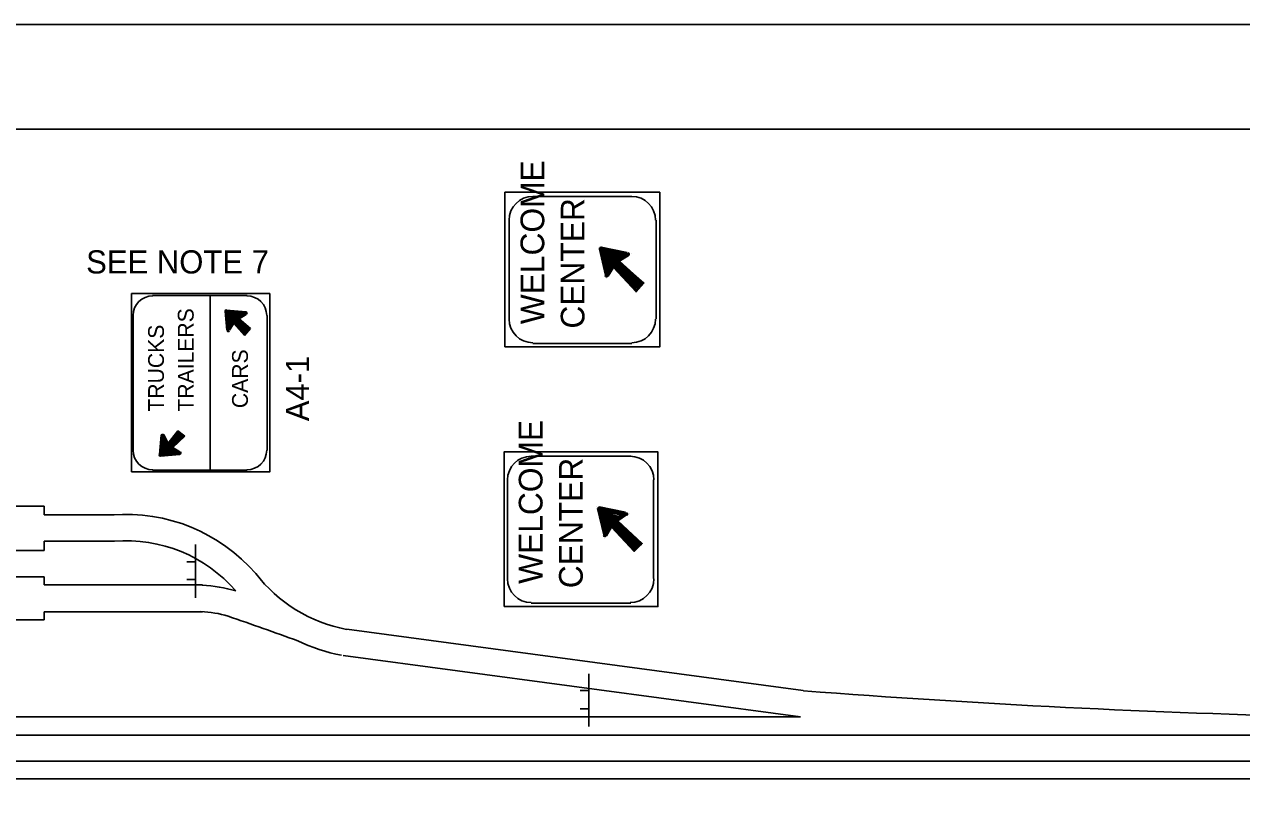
# Model space of a CAD drawing. Extents: x 2189973 to 2192941, y 2147557 to 2151454.
# Drawn here: x 2190575 to 2191146, y 2151094 to 2151454 of the extents above; entities that cross this region are included whole.
import ezdxf

# ---------------------------------------------------------------- set-up
doc = ezdxf.new("R2010")
doc.units = 0
doc.layers.add('Default', color=7, linetype='Continuous')
doc.layers.add('PLT-BNDY', color=7, linetype='Continuous')

msp = doc.modelspace()

# ---------------------------------------------------------------- linework, layer by layer
at = {"layer": 'Default'}
for p, q in [((2190104.48, 2151405.2), (2192683.21, 2151405.2)), ((2190813.55, 2151373.62), (2190859.89, 2151373.62)), ((2190844.31, 2151349.83), (2190844.31, 2151349.83)), ((2190844.72, 2151349.01), (2190847.59, 2151336.71)), ((2190857.84, 2151347.37), (2190845.54, 2151349.83)), ((2190854.15, 2151343.27), (2190858.66, 2151346.14)), ((2190859.89, 2151346.96), (2190859.89, 2151346.96)), ((2190848.82, 2151336.3), (2190851.28, 2151340.4)), ((2190851.28, 2151340.4), (2190851.28, 2151340.4)), ((2190851.28, 2151340.4), (2190861.94, 2151328.92)), ((2190854.15, 2151343.27), (2190854.15, 2151343.27)), ((2190865.63, 2151333.02), (2190854.15, 2151343.27)), ((2190848, 2151335.07), (2190848, 2151335.07)), ((2190861.94, 2151328.92), (2190865.63, 2151333.02)), ((2190635.15, 2151327.28), (2190679.45, 2151327.28)), ((2190662.22, 2151245.26), (2190662.22, 2151327.28)), ((2190669.19, 2151319.9), (2190670.01, 2151310.87)), ((2190679.04, 2151319.49), (2190669.6, 2151320.31)), ((2190669.6, 2151319.9), (2190669.6, 2151319.9)), ((2190675.76, 2151316.2), (2190679.04, 2151318.26)), ((2190675.76, 2151316.2), (2190675.76, 2151316.2)), ((2190681.09, 2151311.69), (2190675.76, 2151316.2)), ((2190679.04, 2151318.67), (2190679.04, 2151318.67)), ((2190679.86, 2151318.67), (2190679.86, 2151318.67)), ((2190679.86, 2151318.67), (2190679.86, 2151318.67)), ((2190670.42, 2151310.87), (2190670.42, 2151310.87)), ((2190673.29, 2151314.15), (2190671.24, 2151310.87)), ((2190673.29, 2151314.15), (2190673.29, 2151314.15)), ((2190673.29, 2151314.15), (2190678.22, 2151308.41)), ((2190674.52, 2151315.38), (2190674.52, 2151315.38)), ((2190678.22, 2151308.41), (2190681.09, 2151311.69)), ((2190681.09, 2151311.69), (2190681.09, 2151311.69)), ((2190670.42, 2151309.64), (2190670.42, 2151309.64)), ((2190670.42, 2151309.64), (2190670.42, 2151309.64)), ((2190678.22, 2151308.41), (2190678.22, 2151308.41)), ((2190859.89, 2151304.72), (2190813.55, 2151304.72)), ((2190873.02, 2151303.08), (2190800.43, 2151303.08)), ((2190639.26, 2151261.66), (2190638.44, 2151252.64)), ((2190640.08, 2151262.48), (2190640.08, 2151262.48)), ((2190640.08, 2151262.48), (2190640.08, 2151262.48)), ((2190640.08, 2151261.66), (2190640.08, 2151261.66)), ((2190642.54, 2151257.97), (2190640.49, 2151262.07)), ((2190647.05, 2151263.71), (2190642.54, 2151257.97)), ((2190644.59, 2151255.92), (2190650.33, 2151261.25)), ((2190647.05, 2151263.71), (2190647.05, 2151263.71)), ((2190650.33, 2151261.25), (2190647.05, 2151263.71)), ((2190650.33, 2151261.25), (2190650.33, 2151261.25)), ((2190642.54, 2151257.97), (2190642.54, 2151257.97)), ((2190643.36, 2151257.15), (2190643.36, 2151257.15)), ((2190644.59, 2151255.92), (2190644.59, 2151255.92)), ((2190644.59, 2151255.92), (2190647.87, 2151253.87)), ((2190647.87, 2151253.46), (2190647.87, 2151253.46)), ((2190648.69, 2151253.46), (2190648.69, 2151253.46)), ((2190648.69, 2151253.46), (2190648.69, 2151253.46)), ((2190638.44, 2151252.23), (2190638.44, 2151252.23)), ((2190638.44, 2151252.23), (2190638.44, 2151252.23)), ((2190638.85, 2151252.64), (2190638.85, 2151252.64)), ((2190638.85, 2151251.82), (2190647.87, 2151252.64)), ((2190812.73, 2151251.82), (2190859.48, 2151251.82)), ((2190633.92, 2151244.44), (2190627.77, 2151244.44)), ((2190635.15, 2151245.26), (2190679.45, 2151245.26)), ((2190663.86, 2151244.44), (2190659.35, 2151244.44)), ((2190510.07, 2151228.44), (2190584.3, 2151228.44)), ((2190584.3, 2151224.34), (2190584.3, 2151228.44)), ((2190843.49, 2151228.03), (2190843.49, 2151228.03)), ((2190843.9, 2151227.21), (2190846.77, 2151214.91)), ((2190857.02, 2151225.57), (2190844.72, 2151228.03)), ((2190859.07, 2151225.16), (2190859.07, 2151225.16)), ((2190584.3, 2151224.34), (2190617.11, 2151224.34)), ((2190853.33, 2151221.47), (2190857.43, 2151224.34)), ((2190853.33, 2151221.47), (2190853.33, 2151221.47)), ((2190864.81, 2151210.81), (2190853.33, 2151221.47)), ((2190847.18, 2151213.27), (2190847.18, 2151213.27)), ((2190848, 2151214.5), (2190850.46, 2151218.6)), ((2190850.46, 2151218.6), (2190850.46, 2151218.6)), ((2190850.46, 2151218.6), (2190861.12, 2151207.12)), ((2190510.07, 2151207.53), (2190584.3, 2151207.53)), ((2190584.3, 2151207.53), (2190584.3, 2151212.04)), ((2190584.3, 2151212.04), (2190617.11, 2151212.04)), ((2190655.25, 2151185.38), (2190655.25, 2151210.4)), ((2190861.12, 2151207.12), (2190864.81, 2151210.81)), ((2190655.25, 2151202.2), (2190651.15, 2151202.2)), ((2190510.07, 2151195.22), (2190584.3, 2151195.22)), ((2190584.3, 2151195.22), (2190584.3, 2151191.53)), ((2190584.3, 2151191.53), (2190658.53, 2151191.53)), ((2190655.25, 2151193.99), (2190651.15, 2151193.99)), ((2190872.19, 2151181.28), (2190800.02, 2151181.28)), ((2190859.48, 2151182.92), (2190812.73, 2151182.92)), ((2190510.07, 2151175.13), (2190584.3, 2151175.13)), ((2190584.3, 2151178.82), (2190584.3, 2151175.13)), ((2190584.3, 2151178.82), (2190658.53, 2151178.82)), ((2190726.2, 2151170.62), (2190940.27, 2151141.91)), ((2190724.56, 2151158.31), (2190724.56, 2151158.31)), ((2190724.56, 2151158.31), (2190939.04, 2151129.61)), ((2190839.8, 2151125.1), (2190839.8, 2151149.7)), ((2190839.8, 2151141.91), (2190835.7, 2151141.91)), ((2190839.8, 2151133.3), (2190835.7, 2151133.3)), ((2190155.33, 2151129.61), (2190939.04, 2151129.61)), ((2190939.04, 2151129.61), (2190939.04, 2151129.61)), ((2190939.04, 2151129.61), (2190939.04, 2151129.61)), ((2190114.32, 2151121), (2192679.93, 2151121)), ((2190114.32, 2151108.69), (2192679.93, 2151108.69)), ((2190114.32, 2151100.49), (2192679.93, 2151100.49))]:
    msp.add_line(p, q, dxfattribs=at)
for points in [[(2190800.43, 2151303.08), (2190800.43, 2151375.67), (2190807.81, 2151375.67), (2190818.88, 2151375.67), (2190826.67, 2151375.67), (2190837.75, 2151375.67), (2190844.31, 2151375.67), (2190866.04, 2151375.67), (2190873.02, 2151375.67), (2190873.02, 2151375.67), (2190873.02, 2151303.08), (2190873.02, 2151303.08)], [(2190802.48, 2151316.2), (2190802.48, 2151362.55)], [(2190871.37, 2151362.55), (2190871.37, 2151316.2)], [(2190861.94, 2151328.92), (2190851.28, 2151340.4), (2190848.82, 2151336.3), (2190848, 2151336.3), (2190847.59, 2151336.71), (2190844.72, 2151349.01), (2190845.13, 2151349.42), (2190845.54, 2151349.83), (2190857.84, 2151346.96), (2190858.66, 2151346.55), (2190857.84, 2151346.14), (2190853.74, 2151343.27), (2190865.63, 2151333.02), (2190861.94, 2151328.92), (2190851.28, 2151340.81), (2190848.41, 2151336.3), (2190848, 2151336.3), (2190848, 2151336.71), (2190845.13, 2151349.01), (2190845.13, 2151349.42), (2190845.54, 2151349.42), (2190857.84, 2151346.96), (2190857.84, 2151346.55), (2190857.84, 2151346.14), (2190853.74, 2151343.27), (2190865.22, 2151333.02), (2190861.94, 2151329.33), (2190851.28, 2151340.81), (2190848.41, 2151336.71), (2190848, 2151336.71), (2190848, 2151336.71), (2190845.13, 2151349.42), (2190857.84, 2151346.55), (2190853.33, 2151343.27), (2190864.81, 2151332.61), (2190861.94, 2151329.74), (2190851.28, 2151341.22), (2190848, 2151336.71), (2190845.54, 2151349.01)], [(2190848.41, 2151337.12), (2190845.54, 2151349.42), (2190857.84, 2151346.55), (2190852.92, 2151343.27), (2190864.81, 2151332.61), (2190861.94, 2151329.74), (2190851.28, 2151341.22), (2190848.41, 2151337.53), (2190846.36, 2151349.01), (2190857.43, 2151346.55), (2190852.92, 2151343.27), (2190864.4, 2151332.61), (2190861.94, 2151330.15), (2190851.28, 2151341.63), (2190848.41, 2151337.94), (2190846.36, 2151348.6), (2190856.61, 2151346.14), (2190852.51, 2151343.27), (2190863.99, 2151332.61), (2190861.94, 2151330.97), (2190851.28, 2151341.63), (2190848.82, 2151338.76), (2190846.77, 2151348.19), (2190855.79, 2151346.14), (2190852.1, 2151343.27), (2190863.58, 2151333.02), (2190861.94, 2151330.97), (2190851.28, 2151342.04), (2190848.82, 2151339.58), (2190847.18, 2151347.78), (2190855.38, 2151346.14), (2190851.69, 2151343.27), (2190863.17, 2151333.02), (2190861.94, 2151331.38), (2190851.28, 2151342.45), (2190848.82, 2151339.99), (2190847.59, 2151347.37), (2190854.56, 2151345.73), (2190851.69, 2151343.27), (2190862.76, 2151333.02), (2190862.76, 2151333.02), (2190861.94, 2151332.2), (2190850.87, 2151342.45), (2190849.23, 2151340.4), (2190848, 2151347.37), (2190854.15, 2151345.73), (2190851.28, 2151343.27), (2190862.35, 2151332.61), (2190861.94, 2151332.61), (2190851.28, 2151342.86), (2190849.23, 2151341.22), (2190848, 2151346.96), (2190853.33, 2151345.73), (2190851.28, 2151343.27), (2190862.35, 2151332.61), (2190861.94, 2151332.61), (2190851.28, 2151343.27), (2190849.64, 2151341.63), (2190848.41, 2151346.55), (2190853.33, 2151345.32), (2190849.64, 2151342.04), (2190848.82, 2151346.14), (2190852.51, 2151345.32), (2190849.64, 2151342.45), (2190849.23, 2151345.73), (2190852.1, 2151345.32), (2190849.64, 2151342.86), (2190849.23, 2151345.73), (2190851.69, 2151344.91), (2190850.05, 2151343.68), (2190849.64, 2151345.32), (2190850.87, 2151344.91), (2190850.05, 2151344.5), (2190850.05, 2151344.91), (2190850.46, 2151344.91)], [(2190625.31, 2151244.44), (2190625.31, 2151328.1), (2190631.05, 2151328.1), (2190638.44, 2151328.1), (2190643.77, 2151328.1), (2190651.56, 2151328.1), (2190656.89, 2151328.1), (2190663.04, 2151328.1), (2190675.34, 2151328.1), (2190690.11, 2151328.1), (2190690.11, 2151244.44), (2190672.47, 2151244.44), (2190665.5, 2151244.44), (2190656.89, 2151244.44), (2190647.46, 2151244.44), (2190635.15, 2151244.44), (2190625.31, 2151244.44)], [(2190626.13, 2151254.69), (2190626.13, 2151317.85)], [(2190669.19, 2151319.9), (2190670.42, 2151311.28), (2190670.42, 2151310.87), (2190670.83, 2151310.46), (2190670.83, 2151310.87), (2190673.29, 2151314.56), (2190673.29, 2151314.56), (2190678.22, 2151308.82), (2190680.68, 2151311.69), (2190675.34, 2151316.2), (2190675.34, 2151316.2), (2190679.04, 2151318.67), (2190679.45, 2151318.67), (2190679.04, 2151319.08), (2190679.04, 2151319.08), (2190669.6, 2151320.31), (2190669.6, 2151320.31), (2190669.19, 2151319.9), (2190669.6, 2151319.9), (2190670.42, 2151310.87), (2190672.88, 2151314.56), (2190678.22, 2151309.23), (2190680.68, 2151311.69), (2190674.93, 2151316.2), (2190679.04, 2151319.08), (2190669.6, 2151319.9), (2190670.42, 2151311.28), (2190672.88, 2151314.97), (2190678.22, 2151309.23), (2190680.27, 2151311.69), (2190674.93, 2151316.2), (2190679.04, 2151318.67), (2190669.6, 2151319.9), (2190670.83, 2151311.69), (2190672.88, 2151314.97), (2190678.22, 2151309.64), (2190679.86, 2151311.69), (2190674.93, 2151316.2), (2190678.63, 2151318.67), (2190670.01, 2151319.49), (2190670.83, 2151312.1), (2190672.88, 2151315.38), (2190678.22, 2151309.64), (2190679.86, 2151311.69), (2190674.52, 2151316.2), (2190678.22, 2151318.67), (2190670.01, 2151319.49), (2190670.83, 2151312.51), (2190672.88, 2151315.38), (2190678.22, 2151310.46), (2190679.45, 2151311.69), (2190674.52, 2151316.2), (2190677.4, 2151318.67), (2190670.42, 2151319.49), (2190671.24, 2151312.92), (2190672.88, 2151315.79), (2190678.22, 2151310.87), (2190679.45, 2151311.69), (2190674.11, 2151316.2), (2190677.4, 2151318.26), (2190670.42, 2151319.08), (2190671.24, 2151313.33), (2190672.88, 2151315.79), (2190678.22, 2151310.87), (2190679.04, 2151311.69), (2190674.11, 2151316.62), (2190676.58, 2151318.26), (2190670.42, 2151319.08), (2190671.24, 2151313.74), (2190672.88, 2151316.2), (2190678.22, 2151311.28), (2190679.04, 2151311.69), (2190674.11, 2151316.62), (2190676.17, 2151318.26), (2190670.83, 2151318.67), (2190671.24, 2151314.15), (2190672.88, 2151316.2), (2190678.22, 2151311.28), (2190678.63, 2151311.69), (2190673.29, 2151316.62), (2190675.76, 2151317.85), (2190671.24, 2151318.67), (2190671.65, 2151314.97), (2190672.88, 2151316.62), (2190678.22, 2151311.69), (2190678.63, 2151311.69), (2190673.29, 2151316.62), (2190675.34, 2151317.85), (2190671.24, 2151318.26), (2190671.65, 2151315.38), (2190672.88, 2151316.62), (2190678.22, 2151311.69), (2190672.88, 2151317.03), (2190674.93, 2151317.85), (2190671.24, 2151318.26), (2190671.65, 2151315.38), (2190672.88, 2151317.03), (2190675.76, 2151314.56), (2190672.88, 2151317.03), (2190674.93, 2151317.85), (2190671.65, 2151317.85)], [(2190671.65, 2151317.85), (2190671.65, 2151316.2), (2190674.52, 2151317.85), (2190671.65, 2151317.85), (2190672.06, 2151316.2), (2190674.11, 2151317.44), (2190672.06, 2151317.85), (2190672.06, 2151316.62), (2190673.29, 2151317.44), (2190672.06, 2151317.44), (2190672.06, 2151317.03), (2190672.88, 2151317.44), (2190672.06, 2151317.44), (2190672.06, 2151317.03), (2190672.47, 2151317.44)], [(2190688.88, 2151317.85), (2190688.88, 2151254.69)], [(2190638.85, 2151252.23), (2190647.46, 2151253.05), (2190647.87, 2151253.05), (2190648.28, 2151253.46), (2190647.87, 2151253.87), (2190644.18, 2151255.92), (2190644.18, 2151256.33), (2190649.92, 2151261.25), (2190647.05, 2151263.71), (2190642.54, 2151257.97), (2190642.54, 2151257.97), (2190640.08, 2151262.07), (2190640.08, 2151262.07), (2190639.67, 2151262.07), (2190639.67, 2151261.66), (2190638.44, 2151252.64), (2190638.44, 2151252.23), (2190638.85, 2151252.23), (2190638.85, 2151252.23), (2190647.87, 2151253.46), (2190644.18, 2151255.92), (2190649.51, 2151261.25), (2190647.05, 2151263.3), (2190642.54, 2151257.56), (2190639.67, 2151262.07), (2190638.85, 2151252.23), (2190647.46, 2151253.46), (2190643.77, 2151255.92), (2190649.51, 2151261.25), (2190647.05, 2151262.89), (2190642.54, 2151257.56), (2190640.08, 2151261.66), (2190638.85, 2151252.64), (2190647.05, 2151253.46), (2190643.77, 2151255.92), (2190648.69, 2151261.25), (2190647.05, 2151262.89), (2190642.54, 2151257.15), (2190640.08, 2151261.25), (2190639.26, 2151252.64), (2190646.64, 2151253.87), (2190643.36, 2151255.92), (2190648.69, 2151261.25), (2190647.05, 2151262.89), (2190642.54, 2151257.15), (2190640.08, 2151260.43), (2190639.26, 2151253.05), (2190646.23, 2151253.87), (2190643.36, 2151255.92), (2190648.28, 2151261.25), (2190647.05, 2151262.48), (2190642.54, 2151256.74), (2190640.08, 2151260.02), (2190639.26, 2151253.05), (2190645.82, 2151253.87), (2190642.95, 2151255.92), (2190647.87, 2151261.25), (2190647.05, 2151262.07), (2190642.54, 2151256.74), (2190640.49, 2151259.61), (2190639.67, 2151253.46), (2190645.41, 2151254.28), (2190642.95, 2151255.92), (2190647.87, 2151261.25), (2190647.05, 2151262.07), (2190642.13, 2151256.74), (2190640.49, 2151259.2), (2190639.67, 2151253.46), (2190645, 2151254.28), (2190642.54, 2151255.92), (2190647.46, 2151261.25), (2190647.05, 2151261.66), (2190642.13, 2151256.33), (2190640.49, 2151258.79), (2190640.08, 2151253.46), (2190644.18, 2151254.28), (2190642.54, 2151255.92), (2190647.46, 2151261.25), (2190647.05, 2151261.66), (2190642.13, 2151256.33), (2190640.9, 2151258.38), (2190640.08, 2151253.87), (2190643.77, 2151254.28), (2190642.13, 2151255.92), (2190647.05, 2151261.25), (2190647.05, 2151261.25), (2190642.13, 2151255.92), (2190640.9, 2151257.97), (2190640.49, 2151254.28), (2190643.36, 2151254.28), (2190642.13, 2151255.92), (2190647.05, 2151261.25), (2190641.72, 2151255.92), (2190640.9, 2151257.56), (2190640.49, 2151254.28), (2190643.36, 2151254.69), (2190641.72, 2151255.51), (2190644.18, 2151257.97), (2190641.72, 2151255.92), (2190640.9, 2151257.15), (2190640.9, 2151254.28)], [(2190640.9, 2151254.28), (2190642.54, 2151254.69), (2190640.9, 2151256.74), (2190640.9, 2151254.69), (2190642.54, 2151254.69), (2190641.31, 2151256.74), (2190640.9, 2151254.69), (2190642.13, 2151255.1), (2190641.31, 2151255.92), (2190641.31, 2151255.1), (2190641.72, 2151255.1), (2190641.31, 2151255.92), (2190641.31, 2151255.1), (2190641.72, 2151255.1), (2190641.31, 2151255.51)], [(2190800.02, 2151181.28), (2190800.02, 2151253.87), (2190806.99, 2151253.87), (2190818.06, 2151253.87), (2190825.85, 2151253.87), (2190836.93, 2151253.87), (2190843.49, 2151253.87), (2190865.22, 2151253.87), (2190872.19, 2151253.87), (2190872.19, 2151253.87), (2190872.19, 2151181.28), (2190872.19, 2151181.28)], [(2190801.66, 2151194.4), (2190801.66, 2151240.75)], [(2190870.14, 2151240.75), (2190870.14, 2151194.4)], [(2190861.12, 2151207.12), (2190850.46, 2151218.6), (2190848, 2151214.5), (2190847.59, 2151214.5), (2190846.77, 2151214.91), (2190843.9, 2151227.21), (2190844.31, 2151227.62), (2190844.72, 2151228.03), (2190857.02, 2151225.16), (2190857.43, 2151224.75), (2190857.43, 2151224.34), (2190853.33, 2151221.47), (2190864.81, 2151210.81), (2190861.12, 2151207.12), (2190850.46, 2151219.01), (2190847.59, 2151214.5), (2190847.59, 2151214.5), (2190847.18, 2151214.91), (2190844.31, 2151227.21), (2190844.31, 2151227.62), (2190844.72, 2151227.62), (2190857.02, 2151225.16), (2190857.43, 2151224.75), (2190857.02, 2151224.34), (2190852.92, 2151221.47), (2190864.4, 2151210.81), (2190861.12, 2151207.53), (2190850.46, 2151219.01), (2190847.59, 2151214.91), (2190847.18, 2151214.91), (2190847.18, 2151214.91), (2190844.31, 2151227.62), (2190857.02, 2151224.75), (2190852.92, 2151221.47), (2190864.4, 2151210.4), (2190861.12, 2151207.94), (2190850.46, 2151219.01), (2190847.59, 2151214.91), (2190844.72, 2151227.21)], [(2190847.59, 2151215.32), (2190844.72, 2151227.62), (2190857.02, 2151224.75), (2190852.51, 2151221.47), (2190863.99, 2151210.4), (2190861.12, 2151207.94), (2190850.46, 2151219.42), (2190847.59, 2151215.73), (2190845.13, 2151227.21), (2190856.61, 2151224.75), (2190852.1, 2151221.47), (2190863.99, 2151210.4), (2190861.12, 2151208.35), (2190850.46, 2151219.83), (2190848, 2151216.14), (2190845.13, 2151226.8), (2190855.79, 2151224.34), (2190851.69, 2151221.47), (2190863.58, 2151210.4), (2190861.12, 2151208.76), (2190850.46, 2151219.83), (2190848, 2151216.96), (2190845.54, 2151226.39), (2190854.97, 2151224.34), (2190851.28, 2151221.47), (2190862.76, 2151210.4), (2190861.12, 2151209.17), (2190850.46, 2151220.24), (2190848, 2151217.78), (2190846.36, 2151225.98), (2190854.56, 2151224.34), (2190851.28, 2151221.47), (2190862.35, 2151210.4), (2190861.12, 2151209.58), (2190850.46, 2151220.65), (2190848.41, 2151218.19), (2190846.77, 2151225.57), (2190853.74, 2151223.52), (2190850.87, 2151221.47), (2190861.94, 2151210.81), (2190861.94, 2151210.81), (2190861.12, 2151209.99), (2190850.46, 2151220.65), (2190848.41, 2151218.6), (2190847.18, 2151225.57), (2190853.33, 2151223.52), (2190850.87, 2151221.47), (2190861.94, 2151210.4), (2190861.12, 2151210.4), (2190850.46, 2151221.06), (2190848.41, 2151219.42), (2190847.18, 2151225.16), (2190852.92, 2151223.52), (2190850.46, 2151221.47), (2190861.53, 2151210.4), (2190861.12, 2151210.4), (2190850.46, 2151221.47), (2190848.82, 2151219.83), (2190847.59, 2151224.75), (2190852.51, 2151223.11), (2190848.82, 2151220.24), (2190848, 2151224.34), (2190852.1, 2151223.11), (2190848.82, 2151220.65), (2190848.41, 2151223.52), (2190851.69, 2151223.11), (2190849.23, 2151221.06), (2190848.82, 2151223.52), (2190850.87, 2151222.7), (2190849.23, 2151221.88), (2190848.82, 2151223.11), (2190850.46, 2151222.7), (2190849.64, 2151222.29), (2190849.23, 2151222.7), (2190849.64, 2151222.7)]]:
    msp.add_lwpolyline(points, dxfattribs=at)
for centre, radius, start, end in [((2190813.53, 2151362.57), 11.13, 90, 180), ((2190859.93, 2151362.57), 11.13, 0, 90), ((2190845.52, 2151349.15), 0.696, 78.0958, 191.9043), ((2190845.52, 2151349.15), 0.696, 78.0958, 191.9043), ((2190857.99, 2151346.52), 0.696, 302.692, 78.0958), ((2190857.99, 2151346.52), 0.696, 302.692, 78.0958), ((2190848.15, 2151336.68), 0.696, 191.9042, 327.308), ((2190848.15, 2151336.68), 0.696, 191.9043, 327.308), ((2190635.27, 2151317.79), 9.28, 90, 180), ((2190679.42, 2151317.79), 9.28, 0, 90), ((2190669.74, 2151319.92), 0.58, 84.0498, 185.9502), ((2190678.83, 2151318.97), 0.58, 301.5539, 84.0498), ((2190813.53, 2151316.18), 11.13, 180, 270), ((2190859.93, 2151316.18), 11.13, 270, 0), ((2190670.68, 2151310.82), 0.58, 185.9502, 328.4461), ((2190639.76, 2151261.49), 0.58, 31.5539, 174.0498), ((2190635.27, 2151254.69), 9.28, 180, 270), ((2190647.91, 2151253.34), 0.58, 275.9502, 58.4461), ((2190679.42, 2151254.69), 9.28, 270, 0), ((2190638.81, 2151252.4), 0.58, 174.0498, 275.9502), ((2190812.76, 2151240.69), 11.13, 90, 180), ((2190859.16, 2151240.69), 11.13, 0, 90), ((2190844.75, 2151227.27), 0.696, 78.0958, 191.9043), ((2190844.75, 2151227.27), 0.696, 78.0958, 191.9043), ((2190857.21, 2151224.64), 0.696, 302.692, 78.0958), ((2190857.21, 2151224.64), 0.696, 302.692, 78.0958), ((2190622.69, 2151144.03), 80.51, 40.8957, 94.5866), ((2190847.37, 2151214.8), 0.696, 191.9042, 327.308), ((2190847.37, 2151214.8), 0.696, 191.9043, 327.308), ((2190622.69, 2151144.03), 68.14, 40.8957, 94.5866), ((2190739.3, 2151239.81), 70.46, 217.6891, 259.2048), ((2190654.99, 2151123.76), 67.66, 73.5134, 87.0474), ((2190812.76, 2151194.3), 11.13, 180, 270), ((2190859.16, 2151194.3), 11.13, 270, 0), ((2190654.99, 2151123.76), 55.29, 73.5134, 87.0474), ((2182157.48, 2127087.3), 25549.51, 70.459164, 70.536636), ((2190739.3, 2151239.81), 82.83, 244.1957, 259.2048), ((2191297.63, 2155830.32), 4702.16, 265.6447, 268.64351)]:
    msp.add_arc(centre, radius, start, end, dxfattribs=at)
at = {"layer": 'PLT-BNDY'}
msp.add_lwpolyline([(2189973.25, 2151454.41), (2192732.43, 2151454.41), (2192732.43, 2149505.6), (2189973.25, 2149505.6)], close=True, dxfattribs=at)

# ---------------------------------------------------------------- texts
at = {"layer": 'Default'}
for s, height, rotation, p in [('WELCOME', 11.129, 90, (2190818.88, 2151313.74)), ('CENTER', 11.129, 90, (2190837.75, 2151311.69)), ('SEE NOTE 7', 10.883, 360, (2190603.99, 2151337.53)), ('TRAILERS', 7.419, 90, (2190654.43, 2151272.73)), ('TRUCKS', 7.419, 90, (2190640.49, 2151272.73)), ('CARS', 7.419, 90, (2190679.86, 2151274.37)), ('A4-1', 10.886, 90, (2190708.56, 2151268.22)), ('WELCOME', 11.129, 90, (2190818.06, 2151191.94)), ('CENTER', 11.129, 90, (2190836.93, 2151189.89))]:
    msp.add_text(s, height=height, rotation=rotation, dxfattribs=at).set_placement(p)

doc.saveas('drawing.dxf')
